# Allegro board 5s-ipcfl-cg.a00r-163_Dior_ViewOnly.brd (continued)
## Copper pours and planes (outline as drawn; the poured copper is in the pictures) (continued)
+3P3VA on BOTTOM (solid shape): 36.61,26.85 36.61,21.95 36.3,21.63 35.66,21.63 35.28,22.01 35.28,24.7 35.12,24.87 34.64,24.87 34.49,25.02 32.95,25.02 32.93,25.04 32.93,25.71 32.94,25.71 34.41,25.71 34.56,25.87 35.13,25.87 35.28,26.02 35.28,26.66 35.48,26.86 36.6,26.86
+3P3VA on BOTTOM (solid shape): 104.9,39.77 104.9,38.04 104.67,37.81 103.22,37.81 103.1,37.94 103.1,39.28 103.01,39.37 103,39.37 102.93,39.44 102.92,39.44 102.86,39.51 98.62,39.51 98.41,39.72 98.41,40.64 98.47,40.71 103.96,40.71
+3P3VA on BOTTOM (solid shape): outline of 841 points within 48.11,35.5 72.87,53.96
+3P3VA on IN2 (solid shape): 119.34,26.03 119.34,25.24 118.68,24.58 116.04,24.58 115.76,24.86 115.76,26.08 116.16,26.49 118.88,26.49
+3P3VA on IN2 (solid shape): 69.78,38.9 69.78,35.89 69.6,35.71 67.33,35.71 67.08,35.96 67.08,39.13 67.27,39.32 69.36,39.32
+3P3VA on IN2 (solid shape): 104.82,39.64 104.82,36.69 104.47,36.34 101.34,36.34 101.07,36.62 101.07,37.79 101.52,37.79 101.52,37.73 101.54,37.67 101.56,37.62 101.58,37.57 101.62,37.52 101.66,37.48 101.7,37.45 101.75,37.42 101.8,37.4 101.86,37.38 101.91,37.38 101.97,37.38 102.03,37.39 102.08,37.41 102.13,37.43 102.18,37.46 102.22,37.5 102.26,37.55 102.29,37.59 102.31,37.65 102.33,37.7 102.34,37.76 102.34,37.81 102.33,37.87 102.31,37.92 102.29,37.98 102.26,38.02 102.22,38.07 102.18,38.11 102.13,38.14 102.08,38.16 102.03,38.18 101.97,38.19 101.91,38.19 101.86,38.19 101.8,38.17 101.75,38.15 101.7,38.12 101.66,38.09 101.62,38.05 101.58,38 101.56,37.95 101.54,37.9 101.52,37.84 101.52,37.79 101.07,37.79 101.07,39.87 101.19,39.99 104.47,39.99
+3P3VA_BST on BOTTOM (solid shape): 110.81,32.89 110.81,32.36 110.61,32.16 109.75,32.16 108.94,31.35 108.94,30.03 108.92,30.01 108.78,30.01 108.76,30.02 108.76,31.72 109.27,32.23 109.27,32.89 109.41,33.03 110.67,33.03
+3P3VA_BST_RC on BOTTOM (solid shape): 110.78,34.5 110.78,34.06 110.51,33.78 108.17,33.78 108.16,33.8 108.16,34.43 108.38,34.65 110.63,34.65
+3P3VA_HG on BOTTOM (solid shape): 110,31.43 110,31.23 109.35,30.58 109.35,30.04 109.34,30.03 109.17,30.03 109.15,30.04 109.15,31.09 109.62,31.56 109.88,31.56
+3P3VA_HG_R on BOTTOM (solid shape): 88.42,32.54 88.42,31.36 88.19,31.13 84.88,31.13 84.75,31.26 84.75,31.67 85.3,31.67 86.03,32.39 87.5,32.39 87.75,32.64 88.32,32.64
+3P3VA_LG on BOTTOM (solid shape): 111.26,31.32 111.26,30.87 110.05,29.66 109.6,29.66 109.56,29.71 109.56,30.15 110.47,31.07 110.47,31.39 110.55,31.47 111.11,31.47
+3P3VA_LG_R_D on BOTTOM (solid shape): 88.52,34.93 88.52,33.67 88.39,33.54 87.73,33.54 87.73,33.9 87.56,34.08 87.55,34.08 87.38,34.25 86.31,34.25 86.13,34.08 84.72,34.08 84.72,34.56 85.11,34.95 88.49,34.95
+3P3VA_PHASE on TOP (solid shape): 83.6,38.81 83.6,31.4 83.4,31.2 78.62,31.2 77.87,31.95 77.87,38.78 78.15,39.06 78.15,39.08 78.33,39.26 83.16,39.26
+3P3VA_PHASE on BOTTOM (solid shape): 108.99,32.83 108.99,32.24 108.56,31.81 108.56,30.07 108.51,30.02 108.36,30.02 108.35,30.04 108.35,30.86 107.88,31.33 107.88,32.02 108.14,32.29 108.14,32.88 108.23,32.97 108.86,32.97
+3P3VA_PHASE on BOTTOM (solid shape): 82.63,37.68 82.63,37.33 81.6,36.31 81.6,34.32 82.19,33.72 86.26,33.72 86.56,34.03 86.8,34.03 87.33,33.49 87.33,32.84 87.27,32.77 82.22,32.77 82.14,32.7 82.14,32.06 81.82,31.73 78.25,31.73 77.92,32.06 77.92,37.49 78.41,37.98 82.33,37.98
+3P3VA_SN_C on BOTTOM (solid shape): 84.14,39.98 84.14,39.41 84.1,39.37 82.86,39.37 82.13,38.65 80.12,38.65 79.99,38.77 79.99,40.04 80.14,40.19 83.93,40.19
+3P3VSB on TOP (solid shape): 25.2,140.58 25.2,140.05 25.04,139.89 23.04,139.89 22.86,140.07 22.86,140.76 22.99,140.88 24.89,140.88
+3P3VSB on TOP (solid shape): 73.91,47.54 73.91,45.46 73.02,44.56 72.88,44.52 72.52,44.52 72.31,44.72 72.31,44.88 71.78,45.41 71.78,47.67 71.91,47.79 73.66,47.79
+3P3VSB on TOP (solid shape): 75.99,64.23 76.24,64.23 77.08,63.39 77.08,62.06 76.53,61.51 75.77,61.51 75.7,61.45 74.69,62.46 74.69,63.4 75.54,64.25 75.97,64.25
+3P3VSB on BOTTOM (solid shape): 18.85,70.32 18.85,68.65 18.74,68.54 18.31,68.54 18.16,68.7 18.16,70.45 18.24,70.53 18.64,70.53
+3P3VSB on BOTTOM (solid shape): 15.7,65.12 16.38,65.12 16.5,65 16.5,62.53 15.44,61.48 14.95,61.48 14.78,61.65 14.78,62.17 15.24,62.63 15.24,65.29 15.52,65.29
+3P3VSB on BOTTOM (solid shape): 66.34,71.01 66.34,69.92 66.14,69.71 65.6,69.18 64.26,69.18 64.13,69.31 64.13,70.32 64.11,70.35 63.47,70.35 63.35,70.47 63.35,71.11 63.47,71.24 66.11,71.24
+3P3VSB on BOTTOM (solid shape): 73.48,45.79 73.48,43.88 73.68,43.68 73.68,43.04 73.44,42.79 71.02,42.79 70.32,43.5 69.8,43.5 69.04,44.26 68.68,44.26 68.62,44.31 68.62,44.49 68.63,44.49 69.19,44.49 69.24,44.54 69.24,44.64 69.21,44.67 68.65,44.67 68.62,44.69 68.62,44.85 68.66,44.89 69.44,44.89 69.83,44.5 70.98,44.5 71.56,44.5 71.86,44.8 71.86,45.86 71.98,45.99 73.28,45.99
+3P3VSB on BOTTOM (solid shape): 45.08,96.41 45.09,96.39 45.2,96.15 45.44,96.03 45.77,95.7 45.77,95.21 45.64,95.09 45.29,95.09 45.13,95.24 45.13,95.29 44.48,95.6 44.6,94.89 44.62,94.88 44.62,94.44 44.52,94.35 43.79,94.35 43.71,94.43 43.71,95.09 43.71,95.09 43.71,95.93 44.36,96.57 44.65,96.57 44.72,96.59 44.78,96.59 44.84,96.6 44.89,96.6
+3P3VSB on BOTTOM (solid shape): outline of 82 points within 3.26,89.01 6.32,112.12
+3P3VSB on IN1 (solid shape): outline of 1234 points within 36.49,88.13 47.17,101.18
+3P3VSB on IN2 (solid shape): outline of 276 points within 72.29,62.65 78.69,70.15
+3P3VSB on IN2 (solid shape): outline of 1716 points within 43.11,87.06 71.63,102.12
+3P3VSB_LAN on TOP (solid shape): 20.79,141.07 20.86,141.07 21.23,140.71 22.43,140.71 22.53,140.6 22.53,140.22 22.38,140.07 21.12,140.07 20.58,140.6 20.57,140.6 20.39,140.78 20.39,141.11 20.46,141.18 20.69,141.18
+3P3VSB_LAN on TOP (solid shape): 22.55,136.72 22.55,135.8 22.18,135.43 19.71,135.43 19.67,135.47 19.67,135.9 19.73,135.96 21.39,135.96 21.59,136.16 21.59,136.92 21.74,137.07 22.2,137.07
+3P3VSB_LAN on BOTTOM (solid shape): 96.01,10.1 95.53,10.1 95.5,10.07 95.5,9.94 95.53,9.91 96.06,9.91 96.06,9.64 96.06,9.64 96.06,9.26 96.06,9.16 96.01,9.11 95.2,9.11 95.05,8.96 95.05,8.3 94.91,8.16 94.02,8.16 93.81,8.37 93.81,8.48 94.33,9.01 94.33,9.38 95.26,10.3 96.01,10.3
+3P3VSB_LAN on BOTTOM (solid shape): 21.09,141.7 21.03,141.64 21.03,140.72 20.98,140.67 20.38,140.67 20.24,140.54 20.24,139.88 20.25,139.87 20.23,139.86 20.07,139.86 20.05,139.87 20.05,140.69 20.1,140.74 20.34,141.05 20.2,141.42 20.2,141.44 20.57,141.8 20.99,141.8
+ADP_19V on TOP (solid shape): 162.49,47.37 162.49,46.2 161.52,45.22 160.91,45.22 160.11,46.02 160.11,46.76 161.05,47.7 162.16,47.7
+ADP_19V on TOP (solid shape): 165.94,84.47 165.94,80.41 165.66,80.13 163.47,80.13 160.93,82.67 160.93,85.23 161.36,85.66 164.74,85.66
+ADP_19V on TOP (solid shape): 34.52,133.42 34.52,131.9 33.55,130.94 31.76,130.94 31.65,131.05 31.65,133.42 31.75,133.52 34.42,133.52
+ADP_19V on TOP (solid shape): 38.48,155.18 38.48,152.64 38.1,152.26 37.13,152.26 36.83,152.57 36.83,155.16 37.03,155.36 38.3,155.36
+ADP_19V on TOP (solid shape): 131.88,20.21 131.88,16.37 131.71,16.21 131.27,16.21 131.1,16.37 130.5,16.37 130.35,16.53 130.35,20.31 130.45,20.41 131.67,20.41
+ADP_19V on TOP (solid shape): 26.75,121 26.77,121 26.77,120.46 26.49,120.18 26.49,119.34 26.35,119.2 25.13,119.2 25.02,119.32 25.02,120.34 25.27,120.59 25.27,120.83 25.83,121.38 26.36,121.38
+ADP_19V on TOP (solid shape): 159.31,167.2 159.31,166.77 159.18,166.64 158.34,166.64 158.04,166.33 158.04,165.34 157.94,165.24 157.35,165.24 157.3,165.29 157.3,166.54 157.4,166.64 157.4,167.22 157.78,167.6 158.9,167.6
+ADP_19V on TOP (solid shape): 82.52,65.55 82.52,64.28 82.52,64.28 82.52,62.22 82.4,62.09 80.87,62.09 80.62,62.35 80.62,64.89 80.49,65.01 80.14,65.01 79.61,65.53 79.46,65.53 79.22,65.78 79.22,66.28 79.31,66.37 81.7,66.37
+ADP_19V on TOP (solid shape): 142.19,10.71 142.19,10.02 141.68,9.51 140.87,9.51 140.52,9.16 139.78,9.16 139.73,9.21 139.73,10.8 139.83,10.9 142,10.9
+ADP_19V on TOP (solid shape): 162.13,151.2 162.13,150.56 162.23,150.46 163.09,150.46 163.22,150.33 163.22,146.57 163.12,146.47 162.2,146.47 161.95,146.22 161.95,145.25 161.69,145 159.15,145 158.55,144.39 158.29,144.39 158.09,144.59 158.09,149.19 158.27,149.37 158.76,149.37 159.28,149.16 159.8,149.37 160.15,149.37 160.68,149.9 160.68,151.15 160.78,151.25 162.08,151.25
+ADP_19V on BOTTOM (solid shape): 33.95,131.43 33.95,130.34 33.49,129.87 32.09,129.87 31.78,130.19 31.78,131.54 31.96,131.72 33.66,131.72
+ADP_19V on BOTTOM (solid shape): 131.88,20.19 131.88,16.24 130.33,16.24 129.92,16.65 129.92,20.26 130.08,20.42 131.65,20.42
+ADP_19V on BOTTOM (solid shape): 111.68,168.8 111.7,168.69 111.73,168.59 111.63,168.28 111.67,167.96 111.62,167.33 112.06,166.87 112.06,166.69 111.61,166.23 109.02,166.23 108.94,166.31 108.94,168.01 109.83,168.9 111.58,168.9
+ADP_19V on BOTTOM (solid shape): outline of 223 points within 20.8,119.88 26.49,129.05
+ADP_19V on BOTTOM (solid shape): outline of 515 points within 122.68,165.88 155.06,171.08
+ADP_19V on IN1 (solid shape): 164.53,46.85 164.53,39.72 164.22,39.42 162.06,39.42 161.65,39.82 161.65,43.95 160.77,44.84 160.77,47.59 160.95,47.77 163.6,47.77
+ADP_19V on IN1 (solid shape): 165.56,70.7 165.56,69.66 165.5,69.3 165.56,68.94 165.56,67.66 165.5,67.3 165.56,66.94 165.56,66.08 164.62,65.14 162.79,65.14 162.62,65.31 162.62,70.92 162.86,71.16 165.1,71.16
+ADP_19V on IN1 (solid shape): 162.56,95.17 162.56,93.27 161.85,90.98 162.56,88.69 162.56,88.68 162.59,88.66 163.02,88.14 163.54,87.71 163.76,87.48 163.76,83.36 163.67,83.27 161.26,83.27 160.21,84.33 160.21,84.92 160.02,85.1 160.02,95.71 162.02,95.71
+ADP_19V on IN1 (solid shape): outline of 857 points within 130,7.52 160.5,22.09
+ADP_19V on IN1 (solid shape): outline of 901 points within 82.14,165.86 110.54,171.05
+ADP_19V on IN2 (solid shape): 84.2,169.61 84.2,168.77 83.89,168.47 81.1,168.47 81.02,168.54 81.02,169.81 81.23,170.02 83.79,170.02
+ADP_19V on IN2 (solid shape): 165.43,70.83 165.43,65.95 164.62,65.14 162.56,65.14 162.08,65.62 162.08,70.96 162.28,71.16 165.1,71.16
+ADP_19V on IN2 (solid shape): 38.53,156.86 38.53,154.29 38.05,153.81 37.23,153.81 36.92,154.13 36.92,156.97 37.03,157.09 38.3,157.09
+ADP_19V on IN2 (solid shape): 154.96,169.05 154.96,167.07 154.63,166.74 153.06,166.74 152.98,166.82 152.98,167.5 153.03,167.64 153.05,167.79 153.05,167.84 153.47,168.25 153.47,169.31 154.71,169.31
+ADP_19V on IN2 (solid shape): 164.55,46.87 164.55,44.88 164.53,44.85 164.53,39.72 164.22,39.42 162.06,39.42 161.65,39.82 161.65,44.03 160.81,44.88 160.81,47.61 160.97,47.77 163.64,47.77
+ADP_19V on IN2 (solid shape): outline of 904 points within 130,7.52 160.5,22.09
+ADP_19V on IN2 (solid shape): outline of 3181 points within 153.69,83.27 168.48,151.7
+ADP_19V on VCC (solid shape): 162.58,94.96 162.58,93.82 161.63,92.87 161.6,92.82 161.59,92.78 161.59,89.42 161.6,89.37 161.63,89.33 163.5,87.47 163.5,84.09 162.73,83.33 161.19,83.33 159.94,84.57 159.94,95.59 160.05,95.7 161.85,95.7
+USB3_FRONT0 on TOP (solid shape): 54.28,14.37 55.7,14.37 55.9,14.16 55.9,13.3 55.62,13.02 53.34,13.02 49.93,16.42 49.93,17.21 50.16,17.44 51.2,17.44
+USB3_FRONT0 on TOP (solid shape): 71.98,24.27 71.98,23.03 72.24,22.77 73.38,22.77 73.51,22.65 73.51,22.14 73.89,21.76 74.6,21.76 74.67,21.68 74.67,20.54 74.52,20.39 74.12,20.39 73.91,20.18 73.91,15.15 74.52,14.54 75.84,14.54 76.02,14.37 76.02,13.1 75.72,12.79 73.48,12.79 72.03,14.24 72.03,15.41 71.6,15.84 71.6,16.32 71.96,16.68 71.98,16.68 72.03,16.73 72.03,20.78 71.85,20.96 69.12,20.96 68.88,21.2 68.88,22.86 70.83,22.86 70.83,24.38 69.31,24.38 69.31,22.86 68.88,22.86 68.88,24.86 69.09,25.06 71.19,25.06
+USB3_FRONT0 on BOTTOM (solid shape): 54.46,19.37 54.43,19.35 53.08,19.35 52.47,18.74 53.08,18.13 53.98,18.13 52.27,16.42 50.57,16.42 50.39,16.6 50.39,18.54 50.58,18.89 50.39,19.23 50.39,20.46 50.72,20.79 51.84,20.79 52.25,20.42 52.65,20.79 52.68,20.79 52.68,21.71 52.7,21.73 52.7,23.08 53.19,23.56 54.46,23.56
+USB3_P7 on BOTTOM (solid shape): 56.39,158.77 56.39,156.05 56.11,155.77 54.25,155.77 54.1,155.92 54.1,158.71 54.25,158.87 56.28,158.87
+USB3_P7 on BOTTOM (solid shape): 63.55,153.13 63.55,151.63 63.65,151.53 63.65,148.3 63.88,148.07 64.21,148.07 64.39,147.89 64.39,147.13 64.29,147.03 63.24,147.03 63.07,147.21 62.18,147.21 61.9,147.49 61.9,149.39 61.58,149.71 61.58,153.52 61.6,153.54 63.14,153.54
+USB3_P8 on TOP (solid shape): 43.52,169.95 51.76,169.95 56.22,165.49 56.22,160.3 55.93,160.01 54.4,160.01 54.16,160.24 54.16,163.09 53.84,163.41 53.84,164.5 50.45,167.9 43.33,167.9 43.18,167.74 43.18,165.29 43.05,165.17 40.26,165.17 40.11,165.32 40.11,167.93 41.5,167.93 41.83,168.26 41.83,169.36 41.78,169.41 40.11,169.41 40.11,169.81 40.27,169.98 43.5,169.98
+USB3_P56 on BOTTOM (solid shape): outline of 299 points within 73.66,150.31 82.88,162.8
+VCORE on TOP (solid shape): outline of 3405 points within 92.76,102.66 146.24,142.33
+VCORE on BOTTOM (solid shape): outline of 6879 points within 92.87,106 146.47,144.61
+VCORE on IN1 (solid shape): outline of 3646 points within 92.89,106.26 147.04,141.88
+VCORE on IN2 (solid shape): outline of 176 points within 92.75,138.83 111.45,142.89
+VCORE on IN2 (solid shape): outline of 2689 points within 115.07,106.2 146.4,141.26
+VTT_A_DDR_VTTSNS on BOTTOM (solid shape): 135.83,27.75 135.98,27.75 136.25,27.66 136.51,27.76 137.19,27.76 137.22,27.73 137.22,27.58 137.19,27.56 136.56,27.56 136.34,27.33 135.56,27.33 135.06,27.84 135.06,27.91 135.37,28.22
+VTT_A_REF on BOTTOM (solid shape): 135.85,29.89 135.85,29.34 136.41,28.78 136.41,28.71 136.54,28.57 137.17,28.57 137.22,28.52 137.22,28.39 137.19,28.37 136.51,28.37 136.25,28.47 135.99,28.38 135.34,29.03 135.34,29.89 135.49,30.05 135.7,30.05
+VTT_DDR on TOP (solid shape): 87.77,67.06 87.77,64.04 90.6,61.2 90.6,60.19 90.8,59.98 91.36,59.98 91.49,60.11 91.49,61.92 91.72,61.92 91.74,61.89 91.74,59.58 91.41,59.25 89.48,59.25 89.1,59.63 89.1,60.67 86.85,62.92 86.85,66.77 86.74,66.88 86.36,66.88 86.25,66.77 86.25,61.53 85.9,61.18 85.39,61.18 85.27,61.31 85.27,63.72 85.27,63.72 85.27,64.8 85.27,64.81 85.27,65.58 85.28,65.6 85.3,65.73 85.28,65.87 85.28,66.16 85.27,66.17 85.27,67.53 85.49,67.76 87.07,67.76
+VTT_DDR on BOTTOM (solid shape): 92.58,50.71 92.58,48.82 92.66,48.74 92.66,48.18 92.53,48.06 92.53,47.74 92.15,47.36 92.15,45.13 91.97,44.95 91.04,44.95 90.66,45.34 90.66,47.65 91.18,48.17 91.47,48.17 91.74,48.45 91.74,49.21 91.74,49.21 91.74,49.29 91.74,49.29 91.74,49.98 91.59,50.13 91.34,50.13 91.21,50.26 91.21,50.61 91.54,50.94 92.35,50.94
+VTT_DDR on BOTTOM (solid shape): 133.21,32.74 133.21,29.18 132.95,28.92 132.95,28.27 133.83,27.38 135.09,27.38 135.47,27 137.55,27 137.58,26.97 137.58,26.51 137.48,26.41 137.32,26.41 137.3,26.44 136.81,26.44 135.53,25.15 134.07,25.15 133.83,25.4 132.43,25.4 132.31,25.42 132.18,25.4 131.89,25.4 131.4,25.88 131.4,32.3 131.42,32.3 131.42,32.35 131.4,32.35 131.4,32.89 131.53,33.02 132.93,33.02
+VTT_DDR on IN2 (solid shape): 92.8,52.56 92.8,50.51 92.18,49.89 91.1,49.89 90.87,50.11 90.87,50.26 90.88,50.47 90.78,50.67 90.78,51.17 90.92,51.32 91.18,51.32 91.62,51.26 91.84,51.65 91.84,52.49 91.92,52.57 92.81,52.57
AMP3_1 on BOTTOM (solid shape): 165.87,51.74 165.87,49.12 165.89,49.11 165.89,47.97 165.81,47.89 165.17,47.89 165.06,48.01 165.06,51.76 165.11,51.82 165.8,51.82
AMP3_2 on BOTTOM (solid shape): 166.81,51.79 166.81,50.3 166.81,50.29 166.81,47.65 166.67,47.51 166.29,47.51 166.14,47.67 166.14,49.62 166.13,49.62 166.13,51.82 166.17,51.86 166.73,51.86
CORE_PWM1_BOOT on BOTTOM (solid shape): 116.59,148.32 116.59,147.66 116.68,147.58 116.68,145.28 116.3,144.9 115.42,144.9 115.31,145 115.31,146.23 115.98,146.9 115.98,148.22 116.12,148.35 116.56,148.35
CORE_PWM1_BOOT_R_C on BOTTOM (solid shape): 119.76,146.13 118.55,144.92 117.16,144.92 117.15,144.93 117.15,146.29 117.23,146.38 118.51,146.38 118.89,146.76 119.76,146.76
CORE_PWM1_EN on BOTTOM (solid shape): 116.59,149.17 116.56,149.14 115.93,149.14 115.17,148.37 115.17,148.07 115.12,148.03 114.73,148.03 114.67,148.09 114.67,148.95 115.09,149.37 116.59,149.37
CORE_PWM1_HG_D_R on TOP (solid shape): 129.01,155.56 129.01,155.31 128.62,154.93 128.62,153.28 128.5,153.15 127.61,153.15 127.48,153.28 127.48,156.2 127.61,156.33 128.24,156.33
CORE_PWM1_LG_D on TOP (solid shape): 130.74,148.9 130.74,147.66 130.58,147.49 128.99,147.49 128.95,147.52 128.95,148.73 129.19,148.96 130.68,148.96
CORE_PWM1_LG_D on BOTTOM (solid shape): 119.84,151.62 119.84,151.25 119.61,151.02 119.02,151.02 118.4,150.39 118.4,149.67 118.38,149.65 117.96,149.65 117.9,149.71 117.9,151.2 118.44,151.74 118.44,151.74 118.56,151.86 119.61,151.86
CORE_PWM1_LG_D_R on TOP (solid shape): 130.42,149.34 130.32,149.24 129.13,149.24 128.65,148.76 128.65,147.49 128.51,147.34 127.54,147.34 127.58,147.38 127.58,149.22 128.16,149.22 129.02,150.07 129.02,150.59 129.08,150.65 130.42,150.65
CORE_PWM1_SW_D on TOP (solid shape): 127.14,153.3 126.94,153.1 126.5,153.1 126.38,153.22 126.38,154.25 126.11,154.52 125.47,154.52 125.4,154.6 125.4,155.11 125.53,155.23 126.15,155.23 126.38,155.46 126.38,155.47 126.62,155.71 127.14,155.71
CORE_PWM1_SW_D on BOTTOM (solid shape): 120.05,150.18 120.05,147.78 119.77,147.5 118.87,147.5 118.85,147.52 118.85,148.28 118.5,148.62 117.88,148.62 117.88,148.89 119.05,148.89 119.25,149.09 119.25,149.62 119.19,149.69 119.18,149.71 119.13,149.8 118.97,149.97 118.97,150.33 119.15,150.51 119.72,150.51
CORE_PWM1_SW_S on TOP (solid shape): 127.13,147.35 127.43,147.04 128.82,147.04 128.82,144.55 128.76,144.49 125.14,144.49 123.15,146.48 122.75,146.48 122.75,147 123.37,147 123.8,147.43 123.8,148.21 127.13,148.21
CORE_PWM1_SW_S on BOTTOM (solid shape): 125.7,145.96 125.69,145.97 124.12,145.97 123.27,146.82 123.27,147.79 123.99,148.51 125.7,148.51
CORE_PWM1_VCC on BOTTOM (solid shape): 116.6,151.18 116.6,149.7 116.53,149.63 114.84,149.63 114.53,149.32 113.58,149.32 113.48,149.41 113.48,150.27 114.02,150.81 114.62,150.81 115.39,151.58 116.2,151.58
CORE_PWM2_BOOT on BOTTOM (solid shape): 100.6,149.14 100.81,149.14 100.84,149.11 100.84,148.5 100.66,148.32 100.66,146.14 100.48,145.96 100.15,145.96 99.94,146.18 99.94,148.7 100.38,149.14 100.6,149.14
CORE_PWM2_BOOT_R_C on BOTTOM (solid shape): 104.42,148.18 104.42,147.49 103.7,146.77 101.9,146.77 101.74,146.94 101.74,148.27 102.21,148.27 102.5,147.98 103.38,147.98 103.68,148.28 104.32,148.28
CORE_PWM2_HG_D on BOTTOM (solid shape): 102.76,149.04 103.28,149.04 103.49,148.83 103.49,148.52 103.27,148.3 102.68,148.3 102.16,148.82 102.16,149.12 102.68,149.12
CORE_PWM2_HG_D_R on TOP (solid shape): 112.88,156.45 112.88,155.69 112.75,155.56 110.64,155.56 110.46,155.38 110.46,153.85 109.84,153.85 109.59,154.1 109.59,156.72 109.66,156.8 112.53,156.8
CORE_PWM2_LG_D on BOTTOM (solid shape): 103.28,151.24 103.28,150.83 103.02,150.57 102.74,150.57 102.59,150.42 102.12,150.42 102.12,150.77 102.74,151.4 103.12,151.4
CORE_PWM2_LG_D_R on TOP (solid shape): 110.52,149.72 111.07,149.72 111.16,149.81 112.53,149.81 112.53,149.38 111.74,148.59 111.74,147.74 111.61,147.6 110.69,147.6 110.2,148.09 109.68,148.09 109.68,149.82 109.76,149.9 110.34,149.9
CORE_PWM2_SW_D on TOP (solid shape): 109.17,156.67 109.17,153.96 109.11,153.89 108.59,153.89 108.49,153.99 108.49,155.12 107.62,155.99 107.62,156.71 107.7,156.79 109.05,156.79
CORE_PWM2_SW_D on BOTTOM (solid shape): 104.49,150.18 104.49,149.24 104.34,149.09 103.64,149.09 103.34,149.34 102.95,149.32 102.74,149.32 102.65,149.4 102.2,149.4 102.15,149.45 102.15,149.67 102.6,149.67 102.67,149.74 102.95,149.74 102.97,149.74 103.25,149.71 103.48,149.87 103.92,150.31 104.37,150.31
CORE_PWM2_SW_S on TOP (solid shape): 109.18,148.72 109.18,147.96 109.81,147.33 110.13,147.33 110.48,146.97 110.48,144.52 106.01,144.52 104.79,145.74 104.79,147.54 105.36,147.54 105.89,148.06 105.89,148.78 105.9,148.8 109.11,148.8
CORE_PWM2_SW_S on BOTTOM (solid shape): 110.44,148.63 110.44,146.43 109.82,145.81 108.57,145.81 107.96,146.43 107.96,148.1 108.64,148.78 110.29,148.78
CORE_PWM2_VCC on BOTTOM (solid shape): 101.96,152.38 101.96,151.58 101.9,151.52 101.05,151.52 100.81,151.28 100.81,150.46 100.76,150.41 100.23,150.41 100.1,150.54 100.1,151.16 99.96,151.3 99.96,151.95 99.96,152.16 100.27,152.47 101.87,152.47
CORE_PWM3_BOOT on TOP (solid shape): 86.45,141.82 86.45,141.49 86.65,141.29 87.43,141.29 87.48,141.24 87.48,140.77 87.29,140.58 86.82,140.58 86.69,140.45 86.69,140.13 86.4,139.84 85.97,139.84 85.88,139.94 85.88,140.07 85.88,140.65 85.38,141.15 85.11,141.15 85.11,141.78 85.2,141.87 86.41,141.87
CORE_PWM3_BOOT_R_C on TOP (solid shape): 86.82,146.42 86.82,145.87 86.81,145.86 86.81,145.29 86.28,144.77 86.28,143.74 86.5,143.53 86.5,142.95 86.39,142.84 85.1,142.84 85.1,145.18 86.37,146.45 86.79,146.45
CORE_PWM3_HG_D on TOP (solid shape): 87.49,144.6 87.49,142.67 87.4,142.58 86.98,142.58 86.79,142.76 86.79,144.64 86.92,144.77 87.32,144.77
CORE_PWM3_HG_D_R on TOP (solid shape): 98.03,155.31 98.03,153.96 97.95,153.89 97.27,153.89 97.27,154.82 97.12,154.96 97.12,155.43 97.27,155.58 97.75,155.58
CORE_PWM3_HG_D_R on BOTTOM (solid shape): 97.74,157.07 98.62,157.07 98.68,157.01 98.68,155.74 98.6,155.67 98.45,155.67 98.17,155.39 98.17,154.4 97.99,154.22 97.15,154.22 96.98,154.4 96.98,154.9 96.98,154.91 96.98,155.34 96.98,155.34 96.98,156.35 96.98,157.07 97.08,157.18 97.63,157.18
CORE_PWM3_LG_D on TOP (solid shape): 90.75,144.97 90.75,143.7 89.64,142.59 88.8,142.59 88.72,142.66 88.72,143.09 88.75,143.1 89.38,143.73 89.38,144.34 90.24,145.2 90.52,145.2
CORE_PWM3_LG_D_R on TOP (solid shape): 100.1,150.18 100.1,148.68 99.82,148.4 98.38,148.4 98.04,148.06 97.2,148.06 97.2,149.89 97.4,150.09 98.18,150.09 98.47,150.38 99.9,150.38
CORE_PWM3_SW_D on TOP (solid shape): 96.75,155.32 96.75,153.96 96.65,153.86 96.06,153.86 95.98,153.94 95.98,155.36 96.14,155.53 96.55,155.53
CORE_PWM3_SW_D on BOTTOM (solid shape): 96.72,154.87 96.59,154.74 95.99,154.74 95.99,156.71 96.45,157.18 96.72,157.18
CORE_PWM3_SW_S on TOP (solid shape): 96.75,148.71 96.75,147.61 97.33,147.03 97.33,144.45 93.1,144.45 92.76,144.79 92.76,148.04 93.6,148.88 96.58,148.88
CORE_PWM3_SW_S on BOTTOM (solid shape): 96.8,148.15 96.8,147.02 96.23,146.45 96.23,146.43 95.35,145.56 94.74,145.56 94.23,146.07 94.23,147.12 94.23,147.12 94.23,148.24 94.72,148.72 96.23,148.72
CORE_PWM3_VCC on TOP (solid shape): 89.3,140.94 90.45,140.94 90.45,139.33 90.28,139.16 89.1,139.16 88.73,139.53 88.73,139.9 88.72,139.91 88.72,141.21 88.79,141.29 88.95,141.29
E16_CLK on BOTTOM (solid shape): 44.12,70.53 44.12,69.88 43.91,69.67 41.84,69.67 41.73,69.78 41.73,70.7 41.83,70.79 43.85,70.79
E16_CS0# on BOTTOM (solid shape): 44.02,64.58 44.02,63.91 43.75,63.64 41.8,63.64 41.63,63.81 41.63,64.73 41.8,64.9 43.7,64.9
E16_IO2 on BOTTOM (solid shape): 44.03,72.66 44.03,71.85 43.92,71.74 41.79,71.74 41.74,71.79 41.74,72.71 41.83,72.79 43.9,72.79
E16_MISO on BOTTOM (solid shape): 44.12,68.57 44.12,67.89 43.77,67.55 41.98,67.55 41.73,67.8 41.73,68.72 41.9,68.88 43.8,68.88
E16_MOSI on BOTTOM (solid shape): 44.07,66.56 44.07,65.89 43.72,65.54 41.93,65.54 41.68,65.79 41.68,66.71 41.85,66.88 43.75,66.88
GT_PWM1_BOOT on TOP (solid shape): 163.06,126.77 163.06,125.34 162.21,124.48 161.75,124.48 161.75,124.89 162.2,125.34 162.2,126.71 162.28,126.79 163.05,126.79
GT_PWM1_BOOT_R_C on TOP (solid shape): 166.11,126.51 166.11,125.62 165.99,125.49 164.95,125.49 164.77,125.31 164.26,125.31 164.13,125.44 164.13,126.56 164.34,126.76 165.86,126.76
GT_PWM1_HG_D on BOTTOM (solid shape): 140.13,151.42 140.13,151.12 140.03,151.02 139.74,151.02 139.47,150.75 139.47,150.23 139.44,150.21 138.86,150.21 138.78,150.28 138.78,151.53 138.83,151.58 139.98,151.58
GT_PWM1_HG_D_R on TOP (solid shape): 140.23,150.64 140.23,150.35 139.54,149.66 138.72,149.66 138.68,149.7 138.68,150.23 139.22,150.77 140.1,150.77
GT_PWM1_HG_D_R on BOTTOM (solid shape): 138.07,151.4 138.07,150.28 138.43,149.93 139.55,149.93 139.67,150.05 139.67,150.66 139.83,150.82 140.1,150.82 140.25,150.67 140.25,149.47 140.12,149.34 137.56,149.34 137.06,149.85 137.06,151.48 137.16,151.58 137.9,151.58
GT_PWM1_LG_D_R on TOP (solid shape): 139.34,144.49 139.34,143.4 138.68,142.74 138.68,141.8 138.53,141.65 137.67,141.65 137.16,142.15 137.16,142.71 137.26,142.81 137.67,142.81 137.97,143.12 137.97,143.63 138.07,143.73 138.28,143.73 138.63,144.08 138.63,144.49 138.76,144.62 139.22,144.62
GT_PWM1_SN on BOTTOM (solid shape): 133.99,147.56 133.68,147.25 131.83,147.25 131.71,147.36 131.71,147.82 131.51,148.02 131.49,148.02 131.28,148.23 131.28,148.57 131.57,148.86 132.51,148.86 132.76,149.11 133,149.11 133.15,149.26 133.99,149.26
GT_PWM1_SW_S on TOP (solid shape): 143.86,149.12 143.86,145.43 143.74,145.3 139.72,145.3 139.44,145.02 135.1,145.02 134.97,145.15 134.97,147.59 135.09,147.7 139.53,147.7 140.05,148.22 140.64,148.22 141.87,149.45 143.53,149.45
GT_PWM1_SW_S on BOTTOM (solid shape): 137.36,148.99 137.44,148.99 137.44,148.99 139.14,148.99 139.23,148.9 139.23,148.39 139.27,148.35 139.27,145.1 139.19,145.02 135.08,145.02 135.08,145.04 134.99,145.13 134.99,148.37 136.03,149.42 136.93,149.42
GT_PWM2_BOOT on BOTTOM (solid shape): 158.23,122.95 158.23,122.44 158.23,122.43 158.02,122.43 158.02,122.44 157.79,122.44 157.57,122.66 157.57,122.88 157.37,123.09 155.91,123.09 155.9,123.1 155.9,123.76 155.93,123.79 157.4,123.79
GT_PWM2_BOOT_R_C on BOTTOM (solid shape): 157.23,121.97 157.23,121.35 156.44,121.35 156.44,120.31 156.61,120.13 156.97,120.13 157.13,119.98 157.13,119.3 157.53,118.89 157.53,118.53 157.33,118.33 156.49,118.33 155.29,119.52 155.29,121.47 155.88,122.06 157.14,122.06
GT_PWM2_HG_D on BOTTOM (solid shape): 158.24,121.06 158.24,120.69 157.97,120.42 156.83,120.42 156.69,120.56 156.69,121.07 156.74,121.12 158.18,121.12
GT_PWM2_HG_D_R on TOP (solid shape): 168.76,103.75 168.76,100.17 168.6,100 167.09,100 167.08,100.01 167.08,102.6 167.11,102.63 167.76,102.63 168.11,102.97 168.11,103.89 168.61,103.89
GT_PWM2_LG_D on BOTTOM (solid shape): 160.55,120.48 161.14,120.48 161.52,120.11 161.52,119.75 161.29,119.52 160.18,119.52 159.89,119.81 159.89,120.21 159.48,120.63 159.48,121.06 159.53,121.12 159.92,121.12
GT_PWM2_LG_D_R on TOP (solid shape): 163.03,101.92 164.21,100.74 164.21,100.22 164.1,100.11 162.02,100.11 162.02,100.8 162.37,101.14 162.37,103.93 162.41,103.97 163.03,103.97
GT_PWM2_SN on TOP (solid shape): 165.66,98.36 165.99,98.03 166.62,98.03 166.88,97.78 166.88,97.25 166.72,97.09 166.37,97.09 166.17,97.29 164.97,97.29 164.97,98 164.72,98.25 164.28,98.25 164.06,98.48 164.06,99.31 164.16,99.42 165.66,99.42
GT_PWM2_SW_S on TOP (solid shape): 167,111.21 167,108.79 166.17,107.96 166.17,103.13 166.69,102.61 166.69,101.23 164.25,101.23 163.44,102.04 163.44,107.86 162.97,108.34 162.53,108.34 162.53,110.33 163.49,111.29 166.92,111.29
GT_PWM2_SW_S on BOTTOM (solid shape): 158.76,121.13 158.76,120.31 158.81,120.27 158.81,119.62 158.93,119.5 159.71,119.5 160.12,119.09 160.12,118.56 160.04,118.48 158.57,118.48 157.83,119.22 157.83,120.13 157.91,120.21 158.32,120.21 158.48,120.36 158.48,121.06 158.56,121.14 158.74,121.14
GT_PWM2_VCC on BOTTOM (solid shape): 158.75,126.79 158.75,126.22 158.78,126.05 158.87,125.91 159.02,125.77 159.02,124.89 160.07,123.83 160.07,122.55 159.94,122.41 159.5,122.41 159.49,122.42 159.49,123.56 158.05,125 158.05,126.1 157.94,126.22 157.94,126.23 157.83,126.33 157.83,126.86 157.88,126.91 158.62,126.91
HDMI_PD on TOP (solid shape): 134.72,158.99 134.72,158.64 134.57,158.49 134.21,158.49 134.09,158.36 134.09,158.03 133.91,157.85 133.6,157.85 133.48,157.98 133.48,158.33 133.32,158.49 132.92,158.49 132.79,158.61 132.79,158.92 132.92,159.04 134.67,159.04
L23_1 on TOP (solid shape): 6.63,19.95 6.63,19.27 6.42,19.07 6.42,18.1 6.81,17.72 7.03,17.72 7.34,17.41 7.34,15.08 7.19,14.93 7.19,14.34 7.09,14.24 6.5,14.24 6.21,14.53 6.21,16.15 6.19,16.17 6.19,16.25 5.39,17.04 5.08,17.35 5.08,19.95 5.1,19.98 5.76,19.98 5.79,20.01 6.58,20.01
LAN_GATE# on TOP (solid shape): 25.2,135.5 25.2,135.24 25.53,134.91 26.01,134.91 26.06,134.86 26.06,134.51 25.96,134.41 25.96,133.64 25.7,133.39 23.63,133.39 23.5,133.52 23.5,134.22 23.8,134.22 24.13,134.56 24.13,135.5 24.18,135.55 25.14,135.55
LDO1_CAP on TOP (solid shape): 16.6,19.2 16.6,18.43 16.61,18.42 16.61,18.37 16.48,18.05 16.61,17.72 16.61,16.68 16.56,16.63 15.72,16.63 15.67,16.68 15.67,17.22 15.86,17.41 15.86,18.01 16.39,18.54 16.39,19.2 16.42,19.22 16.57,19.22
MIC2-VREFO on TOP (solid shape): 35.15,17.29 35.15,16.83 35.18,16.81 35.18,16.8 35.48,16.5 35.48,15.31 34.82,15.31 34.82,15.84 34.44,16.22 34.44,16.53 34.57,16.65 34.57,17.36 34.62,17.41 35.03,17.41
Net_33 on TOP (solid shape): outline of 240 points within 84.79,108.6 91.55,115.36
Net_34 on TOP (solid shape): outline of 230 points within 146.32,91.11 152.06,96.85
Net_35 on TOP (solid shape): outline of 230 points within 146.32,127.11 152.06,132.85
O_TR_CPU+ on BOTTOM (solid shape): 27.11,84.14 26.22,83.24 25.77,84.59
O_TR_CPU+ on BOTTOM (solid shape): 26.88,81.62 26.62,81.36 26.62,80.87 26.13,80.87 26.13,80.87 25.99,80.72 25.54,82.07
O_TR_CPU- on BOTTOM (solid shape): 26.68,86.21 25.78,85.31 25.33,86.66
O_TR_MB+ on BOTTOM (solid shape): 156.66,17.13 156.66,16.07 156.55,15.97 155.8,15.97 154.53,16.6 155.8,17.24 156.55,17.24
O_TR_MB+ on BOTTOM (solid shape): 156.66,14.43 156.66,13.51 156.49,13.35 155.78,13.35 154.51,13.99 155.78,14.62 156.47,14.62
O_TR_MB- on BOTTOM (solid shape): 156.77,19.63 156.77,18.61 156.7,18.53 155.79,18.53 154.52,19.17 155.79,19.8 156.61,19.8
PQ1_G on TOP (solid shape): 165.58,153.08 165.58,152.69 165.48,152.59 162.41,152.59 162.15,152.34 162.15,151.75 162.1,151.7 161.72,151.7 161.67,151.75 161.67,153.08 161.75,153.15 165.5,153.15
PQ21_D on BOTTOM (solid shape): 71.83,101.56 71.83,99.89 72.67,99.05 72.67,97.68 72.31,97.32 70.46,97.32 70.31,97.48 70.31,98.01 70.48,98.19 70.48,99.86 69.59,100.75 69.59,101.69 69.73,101.83 71.56,101.83
PU10_VIN1 on BOTTOM (solid shape): 67.42,44.83 67.42,44.69 67.4,44.67 66.86,44.67 66.83,44.64 66.83,44.54 66.88,44.49 67.41,44.49 67.42,44.48 67.42,44.05 68.07,43.4 68.26,43.4 68.35,43.31 68.35,42.3 68.42,42.23 68.45,42.2 70.39,42.2 70.39,40.86 70.37,40.83 69.59,40.83 69.49,40.94 69.49,41.26 69.47,41.29 69.15,41.29 69.14,41.28 67.86,41.28 66.85,42.3 66.85,43 66.19,43.66 66.19,44.67 66.42,44.9 67.35,44.9
PU10_VIN2 on BOTTOM (solid shape): 66.35,50.11 66.8,50.11 67.08,49.83 67.08,47.56 67.42,47.22 67.42,46.7 67.39,46.67 66.87,46.67 66.85,46.65 66.85,46.52 66.88,46.5 67.39,46.5 67.42,46.47 67.42,46.28 66.67,46.28 66.64,46.35 66.62,46.39 66.53,46.53 66.39,46.62 66.38,46.63 66.34,46.66 66.28,46.73 65.62,46.73 65.4,46.95 65.4,50.26 65.48,50.33 66.13,50.33
PU30_V+ on TOP (solid shape): 158.16,164.76 158.16,163.82 157.66,163.31 157.66,162.78 157.25,162.37 156.36,162.37 156.26,162.47 156.26,163.13 156.44,163.31 156.44,164.51 156.53,164.6 156.95,164.6 157,164.56 157,164.05 157.05,164 157.22,164 157.3,164.07 157.3,164.76 157.4,164.86 158.06,164.86
PU8401_VIN1 on BOTTOM (solid shape): 47.12,46.06 47.12,42.92 46.23,42.92 46.07,43.07 46.07,43.93 46.02,43.98 46.02,44.1 46.03,44.11 45.66,44.74 45.15,44.22 45.13,44.14 45.05,44.11 44.35,44.11 43.92,44.38 43.48,44.11 42.44,44.11 42.42,44.14 42.42,44.26 42.44,44.29 42.95,44.29 43,44.34 43,44.44 42.95,44.49 42.47,44.49 42.42,44.54 42.42,44.9 42.54,45.02 43.4,45.02 43.55,45.17 43.55,45.79 43.55,45.79 43.55,45.94 43.91,46.29 46.88,46.29
PU8401_VIN2 on BOTTOM (solid shape): 43.25,42.61 43.25,41.6 43.48,41.37 43.89,41.37 44.22,41.04 44.79,41.04 45.04,41.29 45.06,41.29 45.38,41.39 45.52,41.7 45.52,41.72 45.67,41.87 46.56,41.87 46.86,42.18 46.9,42.18 47.19,42.05 47.49,42.18 48.44,42.18 49.66,40.96 49.86,40.96 50.15,41.26 52.94,41.26 52.98,41.21 52.98,40.48 51.97,39.46 51.64,39.46 51.26,39.07 51.61,38.65 51.65,38.65 51.65,38.27 50.84,37.45 45.06,37.45 44.24,38.28 44.24,39.74 43.71,40.27 43.51,40.27 43.5,40.28 43.28,40.33 43.06,40.28 43.05,40.27 42.73,40.27 42.55,40.45 42.55,41.88 42.42,42.01 42.42,42.23 42.47,42.28 43,42.28 43.03,42.31 43.03,42.43 42.98,42.48 42.59,42.48 42.59,42.48 42.52,42.48 42.46,42.53 42.46,42.61 42.53,42.69 43.17,42.69
PU8402_VIN1 on BOTTOM (solid shape): 99.34,15.61 99.34,14.65 99.57,14.43 99.57,13.4 99.1,12.93 99.1,12.8 99.08,12.79 99.08,12 98.83,11.75 98.23,11.75 98.2,11.72 97.28,11.72 97.28,11.9 97.86,11.9 97.89,11.93 97.89,12.08 97.86,12.11 97.28,12.11 97.28,12.99 97.14,13.13 97.14,13.96 97.08,14.02 97.08,14.1 96.45,14.72 95.5,14.72 95.27,14.49 93.59,14.49 93.02,15.05 92.48,15.05 92.43,15.1 92.43,15.69 92.53,15.79 99.17,15.79
PU8402_VIN2 on BOTTOM (solid shape): 98.12,10.32 98.22,10.01 98.51,9.87 98.66,9.84 98.8,9.87 99.31,9.37 99.31,8.55 99.16,8.4 98.4,8.4 98.18,8.18 98.18,8.13 97.66,7.61 97.13,7.61 97,7.74 97,8.88 97.28,9.16 97.28,9.9 97.89,9.9 97.92,9.92 97.92,10.07 97.88,10.11 97.28,10.11 97.28,10.28 97.31,10.32
PWM1_SN_D on BOTTOM (solid shape): 128.97,148.29 129.88,148.29 130.06,148.11 130.06,147.57 130.23,147.39 130.23,146.99 130.05,146.81 128.87,146.81 128.86,146.81 127.77,146.81 127.68,146.91 127.68,148.52 128.74,148.52
PWM2_SN_D on BOTTOM (solid shape): 107.36,146.13 107.04,145.81 105.54,145.81 105.21,146.14 105.21,148.23 105.71,148.23 106.24,148.76 107.36,148.76
PWM3_SN_D on BOTTOM (solid shape): 93.17,148.64 93.17,147.13 93.13,147.09 92.47,147.09 92.46,147.1 90.34,147.1 90.25,147.2 90.25,148.53 91.28,148.53 91.45,148.7 93.12,148.7
Q93034_P12567 on BOTTOM (solid shape): 111.94,42 111.94,40.93 112,40.87 112,37.44 111.74,37.18 111.36,37.18 111.31,37.23 111.31,37.64 111.29,37.67 111.08,37.67 111.03,37.61 111.03,37.23 110.99,37.2 110.69,37.2 110.68,37.21 110.68,37.64 110.5,37.82 110.5,38.91 110.64,39.06 111.38,39.06 111.38,39.61 110.97,39.61 110.97,39.06 110.64,39.06 110.65,39.06 110.65,39.82 110.35,40.13 110.35,41.94 110.62,42.2 111.73,42.2
Q93034_PIN8_4 on BOTTOM (solid shape): 110.14,41.69 110.14,40.04 110.14,40.01 110.38,39.77 110.38,39.08 110.27,38.97 110.27,38.02 110.09,37.84 109.53,37.84 109.25,38.12 109.25,39.98 109.25,39.98 109.25,41.71 109.42,41.87 109.96,41.87
REGOUT on TOP (solid shape): 23.85,145.13 23.85,141.93 23.39,141.47 22.99,141.47 22.45,140.93 21.31,140.93 21.23,141.01 21.23,144.49 22.07,145.33 23.65,145.33
REGOUT on BOTTOM (solid shape): 22.78,141.75 22.78,140.28 22.47,139.97 20.65,139.97 20.62,139.94 20.47,139.94 20.45,139.97 20.45,140.45 20.46,140.47 21.06,140.47 21.23,140.64 21.23,141.55 21.64,141.96 22.57,141.96
RING2 on TOP (solid shape): 36.89,17.3 36.89,16.21 36.68,15.99 36.68,15.2 36.6,15.13 36.6,15.11 36.25,15.11 36.13,15.23 35.99,15.31 35.75,15.55 35.75,16.59 35.43,16.91 35.43,17.31 35.56,17.44 36.75,17.44
RING2 on BOTTOM (solid shape): 37.03,16.65 37.03,16.12 36.83,15.92 35.86,15.92 35.71,16.07 35.71,17.06 36.02,17.36 36.32,17.36
RING2 on IN2 (solid shape): 37.12,17.27 37.12,16.17 36.94,15.99 35.89,15.99 35.69,16.2 35.69,17.16 35.91,17.39 37,17.39
RING2 on IN2 (solid shape): 15.22,23.59 15.22,21.56 15.22,21.55 15.22,21.4 15.11,21.3 14.48,21.3 14.15,21.63 14.15,22.56 13.98,22.73 13.42,22.73 13.32,22.83 13.32,23.64 13.5,23.82 15,23.82
RING2_B on TOP (solid shape): outline of 124 points within 34.73,8.38 38.85,16.07
SLEEVE on TOP (solid shape): 34.19,17.19 34.19,16.12 34.57,15.73 34.57,15.11 34.53,15.1 34.26,14.91 34.14,14.59 34.13,14.54 33.83,14.54 33.7,14.67 33.7,14.82 33.39,15.29 32.84,15.18 32.26,14.6 32.26,13.23 32.22,13.19 31.24,13.19 31.22,13.21 31.22,15.85 32.74,17.38 34,17.38
SLEEVE on IN2 (solid shape): 13.87,22.32 13.87,21.68 13.66,21.48 13.55,21.49 13.44,21.46 13.43,21.46 13.34,21.46 13.19,21.31 13.19,21.22 13.19,21.21 13.17,21.08 13.19,20.94 13.19,20.94 13.19,20.72 13.06,20.6 12.35,20.6 12.18,20.77 12.18,21.95 12.18,21.98 12.65,22.44 13.75,22.44
SLEEVE on IN2 (solid shape): 34.29,15.48 34.29,14.21 33.65,13.58 31.85,13.58 31.41,14.02 31.41,14.82 32.79,14.82 32.79,14.77 32.8,14.71 32.82,14.66 32.85,14.61 32.88,14.56 32.92,14.52 32.97,14.49 33.02,14.46 33.07,14.44 33.13,14.42 33.18,14.42 33.24,14.42 33.29,14.43 33.35,14.45 33.4,14.47 33.45,14.5 33.49,14.54 33.53,14.58 33.56,14.63 33.58,14.68 33.6,14.74 33.6,14.8 33.6,14.85 33.6,14.91 33.58,14.96 33.56,15.01 33.53,15.06 33.49,15.11 33.45,15.14 33.4,15.18 33.35,15.2 33.29,15.22 33.24,15.23 33.18,15.23 33.13,15.22 33.07,15.21 33.02,15.19 32.97,15.16 32.92,15.13 32.88,15.09 32.85,15.04 32.82,14.99 32.8,14.94 32.79,14.88 32.79,14.82 31.41,14.82 31.41,15.36 31.55,15.5 32.79,15.5 33.11,15.81 33.96,15.81
SLEEVE_B on TOP (solid shape): 30.62,13.3 30.83,13.09 30.83,12.28 30.25,11.69 29.32,11.69 28.97,12.04 28.97,13.39 28.99,13.41 29.65,13.41 29.66,13.43 29.69,13.43 29.86,13.59 29.86,14.01 30.05,14.21 30.62,14.21
SPK_L+_R on BOTTOM (solid shape): 164.85,48.68 164.85,48.02 164.73,47.9 162.74,47.9 162.45,48.19 162.45,48.58 162.66,48.79 164.74,48.79
SPK_L-_R on BOTTOM (solid shape): 168.56,48.69 168.56,47.83 168.36,47.62 168,47.62 167.57,48.05 167.09,48.05 167.04,48.1 167.04,48.76 167.12,48.84 168.41,48.84
SURGE_IN_C on BOTTOM (solid shape): 3.83,150.31 9.96,150.31 10.41,149.86 10.41,147.62 9.7,146.92 3.13,146.92 2.93,147.11 2.93,150.75 2.94,150.76 3.38,150.76
SURGE_OUT_C on TOP (solid shape): 12.78,162.19 12.78,160.43 4.31,160.43 4.15,160.59 4.15,162.26 4.31,162.42 12.55,162.42
SURGE_OUT_C on BOTTOM (solid shape): 11.73,161.23 11.73,159.4 9.75,157.42 5.82,157.42 5.79,157.44 5.79,161.1 6.17,161.48 11.48,161.48
SURGE_OUT_R on BOTTOM (solid shape): 7.52,163.87 7.52,162.52 7.44,162.45 5.05,162.45 3.91,163.59 3.91,166.06 3.99,166.13 5.26,166.13
TPM_PIN8 on BOTTOM (solid shape): 11.94,65.24 11.94,62.47 11.68,62.22 10.56,62.22 10.15,62.64 9.51,62.64 9.32,62.83 9.32,63.29 9.12,63.49 6.32,63.49 6.12,63.69 6.12,64.25 6.26,64.39 7.63,64.39 7.77,64.53 7.77,65.06 7.83,65.13 9.43,65.13 9.65,64.91 9.65,64.66 9.65,64.66 10.3,64.25 10.54,64.97 10.54,65.08 10.62,65.13 11.49,65.13 11.63,65.27 11.91,65.27
TPM_PIN22 on BOTTOM (solid shape): 15.41,72.92 15.41,72.88 15.42,72.85 15.42,72.51 15.24,72.33 15.24,70.83 15.19,70.78 14.65,70.78 14.53,70.91 14.53,72.66 14.86,72.99 15.34,72.99
V_SA2_DIMM0_CHB on BOTTOM (solid shape): 114.55,50.64 114.55,50.09 114.54,50.09 114.54,49.89 114.27,49.62 114.27,49.06 114.23,49.02 112.93,49.02 112.93,49.51 112.95,49.53 113.22,49.53 113.66,49.98 113.72,49.98 114.03,50.1 114.15,50.41 114.15,50.64 114.22,50.71 114.48,50.71
VCORE_+19V on TOP (solid shape): 168.68,109.49 168.68,104.51 168.61,104.43 167.87,104.43 167.72,104.29 167.72,103.55 167.62,103.45 166.77,103.45 166.77,107.88 167.36,108.47 167.36,109.64 167.47,109.75 168.42,109.75
VCORE_+19V on TOP (solid shape): outline of 92 points within 123.85,144.01 157.53,155.42
VCORE_+19V on TOP (solid shape): outline of 342 points within 89.7,152.16 111.48,163.49
VCORE_+19V on BOTTOM (solid shape): 168.69,112.96 168.69,108.05 168.64,108 166.16,108 165.97,108.19 165.97,112.57 166.04,112.83 166.01,113.09 166.29,113.37 168.28,113.37
VCORE_+19V on BOTTOM (solid shape): outline of 2066 points within 105.83,125.06 168.53,163.95
VCORE_+19V on IN1 (solid shape): outline of 1560 points within 105.5,144.67 158.09,163.44
VCORE_VCC_C on TOP (solid shape): 93.24,168.87 93.24,167.78 92.94,167.48 91.79,167.48 91.57,167.25 91.41,167.25 91.27,167.39 91.27,167.77 91.79,168.29 91.79,168.77 92.05,169.03 93.09,169.03
VD33STB on TOP (solid shape): 8.91,21.86 8.91,21.63 9.14,21.4 9.14,20.28 8.99,20.13 7.91,20.13 7.9,20.14 7.84,20.14 7.77,20.21 7.77,21.17 7.8,21.2 7.8,21.94 7.87,22.01 8.76,22.01
VF2_1 on TOP (solid shape): outline of 143 points within 147.85,161.51 154.56,166.51

Small or netless copper shapes (teardrops, artwork), in the pictures only: 4438 on TOP, 2795 on BOTTOM, 1116 on IN1, 993 on IN2

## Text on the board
